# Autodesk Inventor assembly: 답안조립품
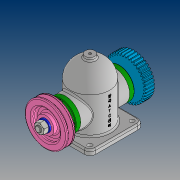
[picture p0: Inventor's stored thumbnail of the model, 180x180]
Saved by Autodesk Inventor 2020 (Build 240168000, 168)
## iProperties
Created: 2021-08
Part Number: 답안조립품
Document SubType Name: Assembly
Designer: PC312-
Author: PC312-
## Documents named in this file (14)
- C:\Users\PC312-\Desktop\710809V1001\답안조립품.iam
- C:\Users\PC312-\Desktop\710809V1001\본체.ipt
- C:\Users\PC312-\Desktop\710809V1001\베어링 6203.ipt
- C:\Users\PC312-\Desktop\710809V1001\축.ipt
- C:\Users\PC312-\Desktop\710809V1001\커버.ipt
- C:\Users\PC312-\Desktop\710809V1001\오일 실 26 38 8.ipt
- C:\Users\PC312-\Desktop\710809V1001\부시.ipt
- C:\Users\PC312-\Desktop\710809V1001\키 5x5x12.ipt
- C:\Users\PC312-\Desktop\710809V1001\V-벨트풀리.ipt
- V-벨트풀리.ipt
- C:\Users\PC312-\Desktop\710809V1001\스퍼기어.ipt
- C:\Users\PC312-\Desktop\710809V1001\너트 M12x1.25.ipt
- C:\Users\PC312-\Desktop\710809V1001\와셔 12x24.ipt
- C:\Users\PC312-\Desktop\710809V1001\볼트 M4.ipt
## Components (1 placed, 1 different names)
1. V-벨트풀리:1
